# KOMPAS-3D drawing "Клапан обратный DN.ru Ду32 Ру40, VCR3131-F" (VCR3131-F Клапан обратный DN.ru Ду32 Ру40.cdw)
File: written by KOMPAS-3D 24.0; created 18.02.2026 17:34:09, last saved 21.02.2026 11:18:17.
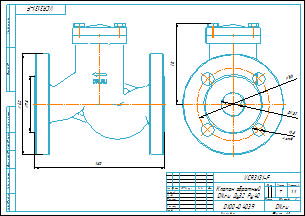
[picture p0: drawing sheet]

Document properties: art: D100-04039; Автор: R2D2; Форматы листов документа: A3; Полное имя файла: VCR3131-F Клапан обратный DN.ru Ду32 Ру40.m3d; Масса: 7; Наименование: Клапан обратный DN.ru Ду32 Ру40; Количество листов документа: 1; Примечание: D100-04039

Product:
- Part/product: Клапан обратный DN.ru Ду32 Ру40  | designation VCR3131-F
    Масса: 7
    Форматы листов документа: A3
    Примечание: D100-04039
    additional columns: D100-04039

Views: Вид 1, Спереди, Проекционный вид 2
Referenced files in E:\Работа\Зайцев\VCR3131-F Клапан обратный DN.ru Ду15-300\DN32\: VCR3131-F Клапан обратный DN.ru Ду32 Ру40.m3d
Referenced files in E:\Работа\Зайцев\Для компаса\: чертеж DN.ru А3.cdt
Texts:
  VCR3131-F
  чертеж DN.ru А3.cdt
  Клапан обратный
  DN.ru Ду32 Ру40
  prop
  Клапан обратный DN.ru Ду32 Ру40
  VCR3131-F Клапан обратный DN.ru Ду32 Ру40
Dimensions and other numbers on the sheet: 0; 3; 2; 4; 100; 18; 4 отв.; 32; 112; 180; 140; 78; 1:1; 1; 7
